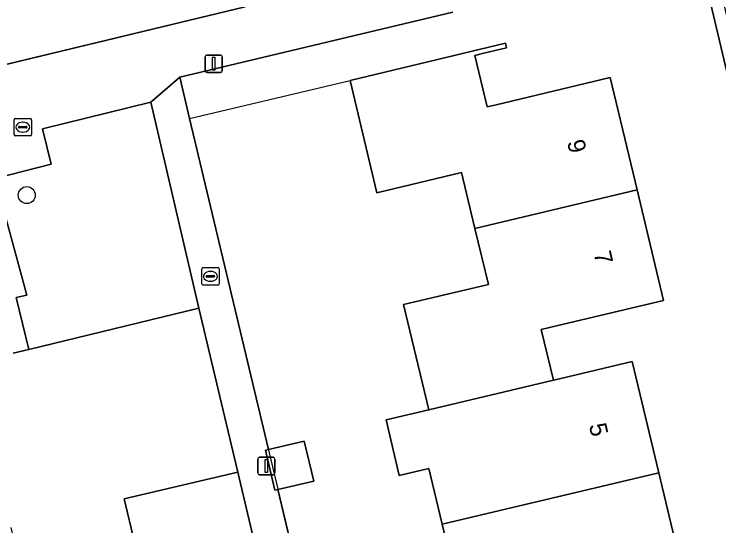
# Model space of a CAD drawing. Extents: x 157648 to 158502, y 379212 to 380938.
# Drawn here: x 158205.38 to 158245.9, y 380798.36 to 380827.8 of the extents above; entities that cross this region are included whole.
import ezdxf

# ---------------------------------------------------------------- set-up
doc = ezdxf.new("R2010")
doc.units = 0
for name, color, linetype in [('IMGEO_Boom', 7, 'Continuous'), ('IMGEO_Erf', 7, 'Continuous'), ('IMGEO_Groenvoorziening', 7, 'Continuous'), ('IMGEO_Hek', 7, 'Continuous'), ('IMGEO_Kolk', 7, 'Continuous'), ('IMGEO_Lichtmast', 7, 'Continuous'), ('IMGEO_Pand', 7, 'Continuous'), ('IMGEO_Pand_nummerreeks', 7, 'Continuous'), ('IMGEO_Rioolput', 7, 'Continuous'), ('IMGEO_Voetpad_open', 7, 'Continuous')]:
    doc.layers.add(name, color=color, linetype=linetype)

msp = doc.modelspace()

# ---------------------------------------------------------------- linework, layer by layer
at = {"layer": 'IMGEO_Boom'}
msp.add_circle((158206.111, 380817.384), 0.489, dxfattribs=at)
at = {"layer": 'IMGEO_Erf'}
for points in [[(158200.29, 380838.795), (158203.704, 380824.608), (158218.664, 380828.221)], [(158254.914, 380788.414), (158245.325, 380828.86)], [(158230.614, 380827.909), (158214.903, 380824.164), (158215.467, 380821.796), (158219.999, 380802.746), (158222.062, 380803.233), (158222.605, 380800.939), (158220.545, 380800.452), (158222.973, 380790.246)], [(158230.754, 380795.234), (158229.989, 380798.448), (158229.224, 380801.662), (158227.526, 380801.257), (158226.765, 380804.451), (158229.218, 380805.036), (158227.776, 380811.084), (158232.648, 380812.245), (158231.88, 380815.465), (158231.113, 380818.684), (158226.246, 380817.523), (158224.705, 380823.985), (158233.638, 380826.115), (158233.699, 380825.858), (158232.394, 380825.547), (158231.869, 380825.422), (158232.576, 380822.455), (158233.101, 380822.58), (158239.657, 380824.143), (158241.197, 380817.685), (158242.712, 380811.332), (158236.166, 380809.771), (158235.691, 380809.658), (158236.388, 380806.732), (158236.807, 380806.832), (158240.921, 380807.813), (158242.446, 380801.418), (158243.944, 380795.133)], [(158205.2, 380798.266), (158206.366, 380793.376), (158209.628, 380794.154), (158212.892, 380794.932), (158211.705, 380799.912), (158218.24, 380801.457), (158215.996, 380810.883), (158206.225, 380808.502), (158205.326, 380808.293)]]:
    msp.add_lwpolyline(points, dxfattribs=at)
at = {"layer": 'IMGEO_Groenvoorziening'}
msp.add_lwpolyline([(158206.225, 380808.502), (158215.996, 380810.883), (158213.234, 380822.726), (158207.011, 380821.205), (158207.513, 380819.159), (158204.271, 380818.337), (158206.107, 380811.638), (158205.49, 380811.494)], close=True, dxfattribs=at)
at = {"layer": 'IMGEO_Hek'}
for points in [[(158218.664, 380828.221), (158203.449, 380824.546)], [(158215.467, 380821.796), (158224.705, 380823.985)], [(158215.467, 380821.796), (158222.973, 380790.246)], [(158206.225, 380808.502), (158215.996, 380810.883)], [(158215.996, 380810.883), (158218.24, 380801.457)]]:
    msp.add_lwpolyline(points, dxfattribs=at)
at = {"layer": 'IMGEO_Kolk'}
for p, q in [((158216.166, 380812.287), (158216.166, 380813.139)), ((158216.241, 380813.213), (158217.093, 380813.213)), ((158217.167, 380813.139), (158217.167, 380812.287)), ((158216.425, 380812.707), (158216.425, 380812.719)), ((158216.863, 380812.67), (158216.465, 380812.67)), ((158216.468, 380812.756), (158216.866, 380812.756)), ((158216.654, 380812.993), (158216.679, 380812.993)), ((158216.909, 380812.719), (158216.909, 380812.707)), ((158217.093, 380812.213), (158216.241, 380812.213)), ((158216.677, 380812.433), (158216.652, 380812.433))]:
    msp.add_line(p, q, dxfattribs=at)
for points in [[(158216.166, 380812.287), (158216.166, 380813.139)], [(158216.241, 380813.213), (158217.093, 380813.213)], [(158217.167, 380813.139), (158217.167, 380812.287)], [(158217.093, 380812.213), (158216.241, 380812.213)]]:
    msp.add_lwpolyline(points, dxfattribs=at)
for centre, radius, start, end in [((158216.243, 380813.137), 0.0765, 91.552, 178.448), ((158216.243, 380813.137), 0.0765, 91.552, 178.448), ((158217.091, 380813.137), 0.0765, 1.552, 88.448), ((158217.091, 380813.137), 0.0765, 1.552, 88.448), ((158216.465, 380812.716), 0.0403, 85.8775, 175.7526), ((158216.462, 380812.706), 0.0366, 178.938, 274.7102), ((158216.866, 380812.713), 0.043, 264.8664, 352.4533), ((158216.87, 380812.718), 0.0386, 1.7309, 96.639), ((158216.243, 380812.289), 0.0765, 181.552, 268.448), ((158216.243, 380812.289), 0.0765, 181.552, 268.448), ((158217.091, 380812.289), 0.0765, 271.552, 358.448), ((158217.091, 380812.289), 0.0765, 271.552, 358.448)]:
    msp.add_arc(centre, radius, start, end, dxfattribs=at)
for centre, major_axis, ratio, start_param, end_param in [((158216.653, 380812.713), (-0.387, 0.002), 0.722429, 4.712389, 7.853982), ((158216.678, 380812.713), (-0.39, 0.002), 0.717154, 1.570796, 4.712389)]:
    msp.add_ellipse(centre, major_axis=major_axis, ratio=ratio, start_param=start_param, end_param=end_param, dxfattribs=at)
at = {"layer": 'IMGEO_Lichtmast'}
for p, q in [((158216.361, 380824.541), (158216.361, 380825.341)), ((158216.361, 380825.341), (158216.361, 380824.541)), ((158216.461, 380825.441), (158217.251, 380825.441)), ((158217.251, 380825.441), (158216.461, 380825.441)), ((158217.351, 380825.341), (158217.351, 380824.541)), ((158217.351, 380824.541), (158217.351, 380825.341)), ((158217.251, 380824.441), (158216.461, 380824.441)), ((158216.461, 380824.441), (158217.251, 380824.441)), ((158219.388, 380801.403), (158219.388, 380802.203)), ((158219.388, 380802.203), (158219.388, 380801.403)), ((158219.488, 380802.303), (158220.278, 380802.303)), ((158220.278, 380802.303), (158219.488, 380802.303)), ((158220.378, 380802.203), (158220.378, 380801.403)), ((158220.378, 380801.403), (158220.378, 380802.203)), ((158220.278, 380801.303), (158219.488, 380801.303)), ((158219.488, 380801.303), (158220.278, 380801.303))]:
    msp.add_line(p, q, dxfattribs=at)
for points in [[(158216.781, 380825.316), (158216.931, 380825.316), (158216.931, 380824.566), (158216.781, 380824.566), (158216.781, 380825.316)], [(158219.808, 380802.178), (158219.958, 380802.178), (158219.958, 380801.428), (158219.808, 380801.428), (158219.808, 380802.178)]]:
    msp.add_lwpolyline(points, dxfattribs=at)
for centre, start, end in [((158216.461, 380825.341), 90, 180), ((158216.461, 380825.341), 90, 180), ((158217.251, 380825.341), 0, 90), ((158217.251, 380825.341), 360, 90), ((158216.461, 380824.541), 180, 270), ((158216.461, 380824.541), 180, 270), ((158217.251, 380824.541), 270, 0), ((158217.251, 380824.541), 270, 0), ((158219.488, 380802.203), 90, 180), ((158219.488, 380802.203), 90, 180), ((158220.278, 380802.203), 0, 90), ((158220.278, 380802.203), 360, 90), ((158219.488, 380801.403), 180, 270), ((158219.488, 380801.403), 180, 270), ((158220.278, 380801.403), 270, 0), ((158220.278, 380801.403), 270, 0)]:
    msp.add_arc(centre, 0.1, start, end, dxfattribs=at)
at = {"layer": 'IMGEO_Pand'}
for points in [[(158241.197, 380817.685), (158239.657, 380824.143), (158233.101, 380822.58), (158232.576, 380822.455), (158231.869, 380825.422), (158232.394, 380825.547), (158233.699, 380825.858), (158233.638, 380826.115), (158224.705, 380823.985), (158226.246, 380817.523), (158231.113, 380818.684), (158231.88, 380815.465)], [(158229.218, 380805.036), (158236.388, 380806.732), (158235.691, 380809.658), (158236.166, 380809.771), (158242.712, 380811.332), (158241.197, 380817.685), (158231.88, 380815.465), (158232.648, 380812.245), (158227.776, 380811.084)], [(158229.218, 380805.036), (158226.765, 380804.451), (158227.526, 380801.257), (158229.224, 380801.662), (158229.989, 380798.448), (158242.446, 380801.418), (158240.921, 380807.813), (158236.807, 380806.832), (158236.388, 380806.732)], [(158219.999, 380802.746), (158219.83, 380802.706), (158220.372, 380800.411), (158220.545, 380800.452), (158222.605, 380800.939), (158222.062, 380803.233)], [(158211.851, 380784.827), (158218.399, 380786.387), (158216.848, 380792.948), (158216.722, 380793.479), (158219.673, 380794.176), (158219.797, 380793.651), (158220.064, 380792.521), (158220.337, 380792.586), (158218.24, 380801.457), (158211.705, 380799.912), (158212.892, 380794.932), (158209.628, 380794.154)], [(158229.989, 380798.448), (158230.754, 380795.234), (158228.997, 380794.815), (158229.727, 380791.753), (158243.944, 380795.133), (158242.446, 380801.418)]]:
    msp.add_lwpolyline(points, close=True, dxfattribs=at)
at = {"layer": 'IMGEO_Rioolput'}
for p, q in [((158205.38, 380820.866), (158205.38, 380821.718)), ((158205.455, 380821.792), (158206.307, 380821.792)), ((158205.868, 380821.572), (158205.893, 380821.572)), ((158206.381, 380821.718), (158206.381, 380820.866)), ((158205.639, 380821.286), (158205.639, 380821.298)), ((158206.077, 380821.249), (158205.679, 380821.249)), ((158205.682, 380821.335), (158206.08, 380821.335)), ((158206.123, 380821.298), (158206.123, 380821.286)), ((158206.307, 380820.792), (158205.455, 380820.792)), ((158205.891, 380821.012), (158205.866, 380821.012))]:
    msp.add_line(p, q, dxfattribs=at)
for points in [[(158205.38, 380820.866), (158205.38, 380821.718)], [(158205.455, 380821.792), (158206.307, 380821.792)], [(158206.381, 380821.718), (158206.381, 380820.866)], [(158206.307, 380820.792), (158205.455, 380820.792)]]:
    msp.add_lwpolyline(points, dxfattribs=at)
for centre, radius, start, end in [((158205.457, 380821.716), 0.0765, 91.552, 178.448), ((158205.457, 380821.716), 0.0765, 91.552, 178.448), ((158206.305, 380821.716), 0.0765, 1.552, 88.448), ((158206.305, 380821.716), 0.0765, 1.552, 88.448), ((158205.679, 380821.295), 0.0403, 85.8775, 175.7526), ((158205.676, 380821.285), 0.0366, 178.938, 274.7102), ((158206.08, 380821.292), 0.043, 264.8664, 352.4533), ((158206.084, 380821.297), 0.0386, 1.7309, 96.639), ((158205.457, 380820.868), 0.0765, 181.552, 268.448), ((158205.457, 380820.868), 0.0765, 181.552, 268.448), ((158206.305, 380820.868), 0.0765, 271.552, 358.448), ((158206.305, 380820.868), 0.0765, 271.552, 358.448)]:
    msp.add_arc(centre, radius, start, end, dxfattribs=at)
for centre, major_axis, ratio, start_param, end_param in [((158205.867, 380821.292), (-0.387, 0.002), 0.722429, 4.712389, 7.853982), ((158205.892, 380821.292), (-0.39, 0.002), 0.717154, 1.570796, 4.712389)]:
    msp.add_ellipse(centre, major_axis=major_axis, ratio=ratio, start_param=start_param, end_param=end_param, dxfattribs=at)
at = {"layer": 'IMGEO_Voetpad_open'}
for points in [[(158245.826, 380829.995), (158244.724, 380830.856), (158245.325, 380828.86), (158254.914, 380788.414), (158255.555, 380788.565)], [(158219.83, 380802.706), (158219.999, 380802.746), (158215.467, 380821.796), (158214.903, 380824.164), (158213.234, 380822.726), (158215.996, 380810.883), (158218.24, 380801.457), (158220.337, 380792.586), (158220.598, 380791.484), (158222.164, 380785.085), (158223.26, 380780.934), (158225.024, 380781.358), (158224.797, 380782.357), (158222.973, 380790.246), (158220.545, 380800.452), (158220.372, 380800.411)]]:
    msp.add_lwpolyline(points, close=True, dxfattribs=at)
for points in [[(158218.664, 380828.221), (158203.704, 380824.608)], [(158205.326, 380808.293), (158206.225, 380808.502), (158205.49, 380811.494), (158206.107, 380811.638), (158204.271, 380818.337), (158207.513, 380819.159), (158207.011, 380821.205), (158213.234, 380822.726), (158214.903, 380824.164), (158230.614, 380827.909)]]:
    msp.add_lwpolyline(points, dxfattribs=at)

# ---------------------------------------------------------------- texts
at = {"layer": 'IMGEO_Pand_nummerreeks'}
for s, rotation, p in [('9', 283.4126, (158237.166, 380820.448)), ('7', 283.4126, (158238.693, 380814.042)), ('5', 283.4112, (158238.423, 380804.145))]:
    msp.add_text(s, height=1, rotation=rotation, dxfattribs=at).set_placement(p)

doc.saveas('drawing.dxf')
